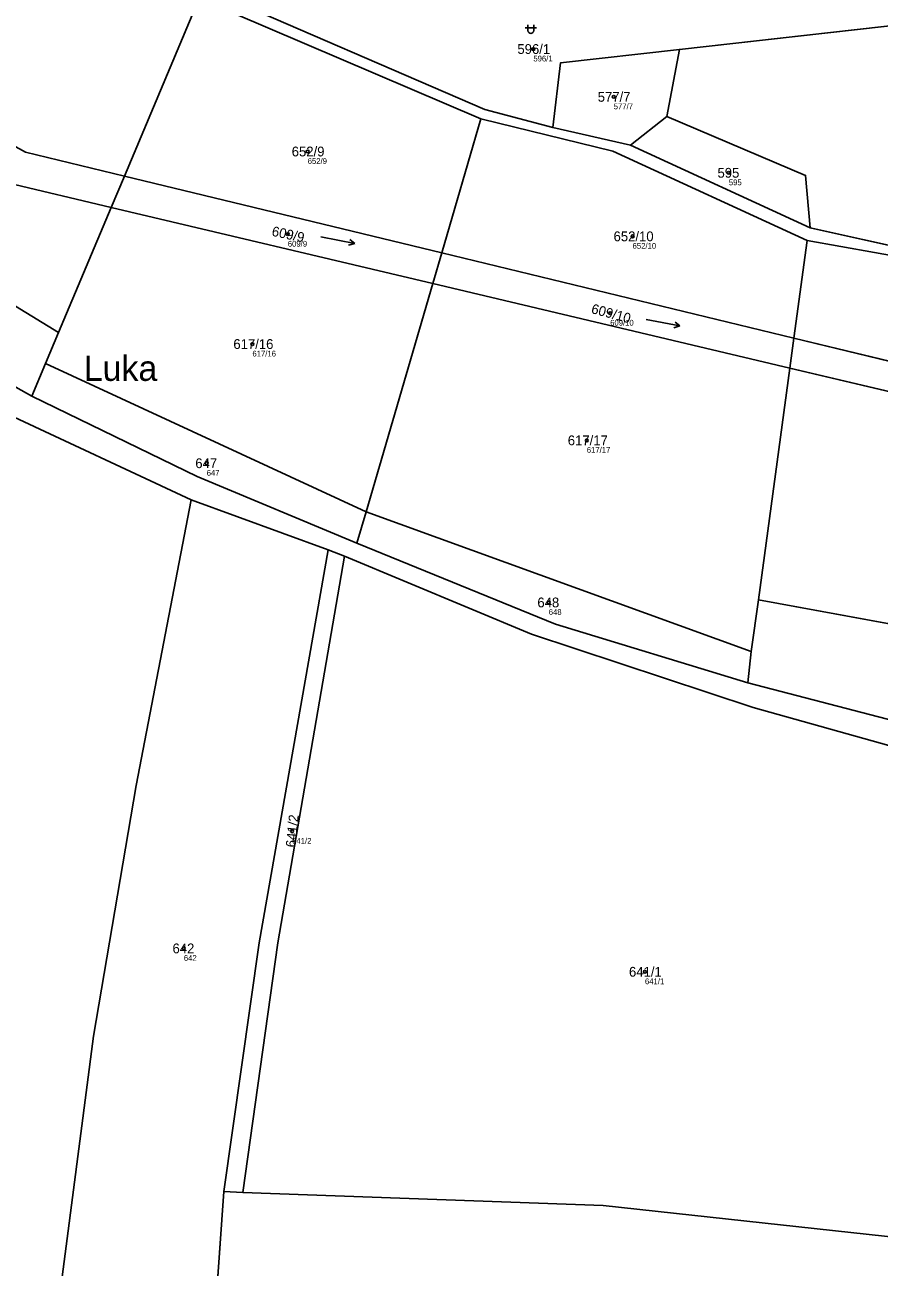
# Model space of a CAD drawing. Extents: x -767985 to -763816, y -1059600 to -1057360.
# Drawn here: x -764998 to -764849.6, y -1059284.4 to -1059068.8 of the extents above; entities that cross this region are included whole.
import ezdxf

# ---------------------------------------------------------------- set-up
doc = ezdxf.new("R2010")
doc.units = 0
for name, color, linetype in [('Definiční body', 7, 'Continuous'), ('Hranice parcel', 7, 'Continuous'), ('Parcelní čísla', 7, 'Continuous'), ('Polygon parcely', 7, 'Continuous'), ('Pop  PČ popisy', 7, 'Continuous'), ('Značky kultur', 7, 'Continuous')]:
    doc.layers.add(name, color=color, linetype=linetype)

msp = doc.modelspace()

# ---------------------------------------------------------------- linework, layer by layer
at = {"layer": 'Definiční body'}
for centre in [(-764909.65, -1059072.95994), (-764895.7, -1059081.25994), (-764948.84, -1059090.74994), (-764875.7, -1059094.44994), (-764952.29, -1059105.10994), (-764892.42, -1059105.47994), (-764896.31, -1059118.81994), (-764958.44, -1059124.17994), (-764900.37, -1059140.89994), (-764966.38, -1059144.86994), (-764906.98, -1059169.03994), (-764951.54, -1059208.76994), (-764970.34, -1059229.09994), (-764890.27, -1059233.15994)]:
    msp.add_circle(centre, 0.25, dxfattribs=at)
at = {"layer": 'Hranice parcel'}
for p, q in [((-764756.52, -1059058.65), (-764884.29, -1059073.04)), ((-764980.66, -1059095.02), (-764967.66, -1059064.11)), ((-764967.66, -1059064.11), (-764918.75, -1059085.08)), ((-764886.5, -1059084.66), (-764884.29, -1059073.04)), ((-764925.55, -1059108.35), (-764918.75, -1059085.08)), ((-764892.8, -1059089.65), (-764886.5, -1059084.66)), ((-764886.5, -1059084.66), (-764862.38, -1059094.9)), ((-764892.8, -1059089.65), (-764906.25, -1059086.6)), ((-764861.6, -1059104.01), (-764892.8, -1059089.65)), ((-764980.66, -1059095.02), (-764982.96, -1059100.47)), ((-764925.55, -1059108.35), (-764980.66, -1059095.02)), ((-764862.38, -1059094.9), (-764861.6, -1059104.01)), ((-764992.09, -1059122.18), (-764982.96, -1059100.47)), ((-764982.96, -1059100.47), (-764927.11, -1059113.69)), ((-764807.24, -1059116.05), (-764861.6, -1059104.01)), ((-764864.39, -1059123.15), (-764862.08, -1059106.19)), ((-764927.11, -1059113.69), (-764925.55, -1059108.35)), ((-764864.39, -1059123.15), (-764925.55, -1059108.35)), ((-764938.69, -1059153.28), (-764927.11, -1059113.69)), ((-764927.11, -1059113.69), (-764865.1, -1059128.36)), ((-764992.09, -1059122.18), (-764994.36, -1059127.58)), ((-764865.1, -1059128.36), (-764864.39, -1059123.15)), ((-764809.41, -1059136.46), (-764864.39, -1059123.15)), ((-764996.73, -1059133.21), (-764994.36, -1059127.58)), ((-764994.36, -1059127.58), (-764938.69, -1059153.28)), ((-764870.58, -1059168.56), (-764865.1, -1059128.36)), ((-764865.1, -1059128.36), (-764809.95, -1059141.41)), ((-764969.08, -1059151.21), (-764945.3, -1059159.91)), ((-764940.29, -1059158.74), (-764938.69, -1059153.28)), ((-764938.69, -1059153.28), (-764871.81, -1059177.56)), ((-764945.3, -1059159.91), (-764942.47, -1059160.99)), ((-764871.81, -1059177.56), (-764870.58, -1059168.56)), ((-764870.58, -1059168.56), (-764814.01, -1059178.97)), ((-764872.39, -1059183.02), (-764871.81, -1059177.56)), ((-764963.4, -1059271.33), (-764965.58, -1059302.41)), ((-764960.13, -1059271.45), (-764963.4, -1059271.33))]:
    msp.add_line(p, q, dxfattribs=at)
for points in [[(-764980.66, -1059095.02), (-764997.85, -1059090.86), (-765067.56, -1059052.35)], [(-764982.96, -1059100.47), (-765000.98, -1059096.21), (-765069.38, -1059057.63)], [(-764906.25, -1059086.6), (-764918.06, -1059083.43), (-764966.27, -1059062.57)], [(-765073.63, -1059069.94), (-765019.49, -1059105.46), (-764992.09, -1059122.18)], [(-764884.29, -1059073.04), (-764904.96, -1059075.37), (-764906.25, -1059086.6)], [(-764996.73, -1059133.21), (-765012.05, -1059124.66), (-765078.11, -1059082.38)], [(-764918.75, -1059085.08), (-764895.84, -1059090.69), (-764862.08, -1059106.19)], [(-764862.08, -1059106.19), (-764838.7, -1059110.37), (-764809.54, -1059118.72), (-764808.5, -1059128.14)], [(-764969.08, -1059151.21), (-765001.55, -1059136.08), (-765045.15, -1059110.12)], [(-764940.29, -1059158.74), (-764968.04, -1059147.17), (-764996.73, -1059133.21)], [(-764993.16, -1059299.02), (-764986.03, -1059244.31), (-764978.64, -1059200.79), (-764969.08, -1059151.21)], [(-764945.3, -1059159.91), (-764957.28, -1059228.13), (-764963.4, -1059271.33)], [(-764872.39, -1059183.02), (-764905.79, -1059172.81), (-764940.29, -1059158.74)], [(-764942.47, -1059160.99), (-764954.01, -1059228.12), (-764960.13, -1059271.45)], [(-764942.47, -1059160.99), (-764909.95, -1059174.57), (-764871.48, -1059187.27), (-764846.5, -1059194.25), (-764815.46, -1059201.74)], [(-764815.93, -1059196.03), (-764845.49, -1059190.02), (-764872.39, -1059183.02)], [(-764823.73, -1059281.76), (-764897.51, -1059273.71), (-764960.13, -1059271.45)]]:
    msp.add_lwpolyline(points, dxfattribs=at)
at = {"layer": 'Polygon parcely'}
for points in [[(-764966.27, -1059062.57), (-765060.07, -1059031.27), (-765151.17, -1058992.96), (-765171.68, -1058981.24), (-765190.33, -1058964.43), (-765190.34, -1058968.18), (-765173.39, -1058982.83), (-765152.48, -1058995.15), (-765060.83, -1059032.86), (-764967.66, -1059064.11), (-764918.75, -1059085.08), (-764895.84, -1059090.69), (-764862.08, -1059106.19), (-764838.7, -1059110.37), (-764809.54, -1059118.72), (-764808.5, -1059128.14), (-764806.78, -1059126.58), (-764807.24, -1059116.05), (-764861.6, -1059104.01), (-764892.8, -1059089.65), (-764906.25, -1059086.6), (-764918.06, -1059083.43)], [(-764980.66, -1059095.02), (-764967.66, -1059064.11), (-765060.83, -1059032.86), (-765067.56, -1059052.35), (-764997.85, -1059090.86)], [(-764752.02, -1059034.29), (-764758.51, -1059035.68), (-764764.34, -1059049.21), (-764818.31, -1059061.96), (-764833.85, -1059056.84), (-764858.96, -1059063.02), (-764885.92, -1059065.02), (-764927.24, -1059059.28), (-764957.74, -1059052.39), (-764966.27, -1059062.57), (-764918.06, -1059083.43), (-764906.25, -1059086.6), (-764904.96, -1059075.37), (-764884.29, -1059073.04), (-764756.52, -1059058.65)], [(-764980.66, -1059095.02), (-764997.85, -1059090.86), (-765067.56, -1059052.35), (-765069.38, -1059057.63), (-765000.98, -1059096.21), (-764982.96, -1059100.47)], [(-764992.09, -1059122.18), (-764982.96, -1059100.47), (-765000.98, -1059096.21), (-765069.38, -1059057.63), (-765073.63, -1059069.94), (-765019.49, -1059105.46)], [(-764862.38, -1059094.9), (-764861.6, -1059104.01), (-764807.24, -1059116.05), (-764759.08, -1059120.3), (-764757.7, -1059074.31), (-764756.52, -1059058.65), (-764884.29, -1059073.04), (-764886.5, -1059084.66)], [(-764925.55, -1059108.35), (-764918.75, -1059085.08), (-764967.66, -1059064.11), (-764980.66, -1059095.02)], [(-764996.73, -1059133.21), (-764994.36, -1059127.58), (-764992.09, -1059122.18), (-765019.49, -1059105.46), (-765073.63, -1059069.94), (-765076.21, -1059077.43), (-765078.11, -1059082.38), (-765012.05, -1059124.66)], [(-764892.8, -1059089.65), (-764886.5, -1059084.66), (-764884.29, -1059073.04), (-764904.96, -1059075.37), (-764906.25, -1059086.6)], [(-764940.29, -1059158.74), (-764968.04, -1059147.17), (-764996.73, -1059133.21), (-765012.05, -1059124.66), (-765078.11, -1059082.38), (-765079.83, -1059086.87), (-765045.15, -1059110.12), (-765001.55, -1059136.08), (-764969.08, -1059151.21), (-764945.3, -1059159.91), (-764942.47, -1059160.99), (-764909.95, -1059174.57), (-764871.48, -1059187.27), (-764846.5, -1059194.25), (-764815.46, -1059201.74), (-764815.93, -1059196.03), (-764845.49, -1059190.02), (-764872.39, -1059183.02), (-764905.79, -1059172.81)], [(-764862.08, -1059106.19), (-764895.84, -1059090.69), (-764918.75, -1059085.08), (-764925.55, -1059108.35), (-764864.39, -1059123.15)], [(-764892.8, -1059089.65), (-764861.6, -1059104.01), (-764862.38, -1059094.9), (-764886.5, -1059084.66)], [(-764982.96, -1059100.47), (-764927.11, -1059113.69), (-764925.55, -1059108.35), (-764980.66, -1059095.02)], [(-764938.69, -1059153.28), (-764927.11, -1059113.69), (-764982.96, -1059100.47), (-764992.09, -1059122.18), (-764994.36, -1059127.58)], [(-764808.5, -1059128.14), (-764809.54, -1059118.72), (-764838.7, -1059110.37), (-764862.08, -1059106.19), (-764864.39, -1059123.15), (-764809.41, -1059136.46)], [(-764864.39, -1059123.15), (-764925.55, -1059108.35), (-764927.11, -1059113.69), (-764865.1, -1059128.36)], [(-764993.16, -1059299.02), (-764986.03, -1059244.31), (-764978.64, -1059200.79), (-764969.08, -1059151.21), (-765001.55, -1059136.08), (-765045.15, -1059110.12), (-765052, -1059130.58), (-765061.13, -1059169.33), (-765065.58, -1059198.93), (-765074.87, -1059288.96)], [(-764870.58, -1059168.56), (-764865.1, -1059128.36), (-764927.11, -1059113.69), (-764938.69, -1059153.28), (-764871.81, -1059177.56)], [(-764809.41, -1059136.46), (-764864.39, -1059123.15), (-764865.1, -1059128.36), (-764809.95, -1059141.41)], [(-764940.29, -1059158.74), (-764938.69, -1059153.28), (-764994.36, -1059127.58), (-764996.73, -1059133.21), (-764968.04, -1059147.17)], [(-764814.01, -1059178.97), (-764809.95, -1059141.41), (-764865.1, -1059128.36), (-764870.58, -1059168.56)], [(-764993.16, -1059299.02), (-764965.58, -1059302.41), (-764963.4, -1059271.33), (-764957.28, -1059228.13), (-764945.3, -1059159.91), (-764969.08, -1059151.21), (-764978.64, -1059200.79), (-764986.03, -1059244.31)], [(-764871.81, -1059177.56), (-764938.69, -1059153.28), (-764940.29, -1059158.74), (-764905.79, -1059172.81), (-764872.39, -1059183.02)], [(-764945.3, -1059159.91), (-764957.28, -1059228.13), (-764963.4, -1059271.33), (-764960.13, -1059271.45), (-764954.01, -1059228.12), (-764942.47, -1059160.99)], [(-764820.28, -1059238.28), (-764815.46, -1059201.74), (-764846.5, -1059194.25), (-764871.48, -1059187.27), (-764909.95, -1059174.57), (-764942.47, -1059160.99), (-764954.01, -1059228.12), (-764960.13, -1059271.45), (-764897.51, -1059273.71), (-764823.73, -1059281.76)], [(-764815.93, -1059196.03), (-764814.01, -1059178.97), (-764870.58, -1059168.56), (-764871.81, -1059177.56), (-764872.39, -1059183.02), (-764845.49, -1059190.02)], [(-764824.88, -1059315.59), (-764823.73, -1059281.76), (-764897.51, -1059273.71), (-764960.13, -1059271.45), (-764963.4, -1059271.33), (-764965.58, -1059302.41), (-764965.02, -1059316.8)]]:
    msp.add_lwpolyline(points, close=True, dxfattribs=at)
at = {"layer": 'Značky kultur'}
for p, q in [((-764911.091, -1059069.261), (-764909.089, -1059069.261)), ((-764910.591, -1059068.761), (-764910.591, -1059069.762)), ((-764909.589, -1059069.762), (-764909.589, -1059068.761)), ((-764946.57, -1059105.579), (-764940.68, -1059106.724)), ((-764940.68, -1059106.724), (-764941.735, -1059107.03)), ((-764940.68, -1059106.724), (-764941.543, -1059106.045)), ((-764890.08, -1059119.899), (-764884.19, -1059121.044)), ((-764884.19, -1059121.044), (-764885.245, -1059121.35)), ((-764884.19, -1059121.044), (-764885.053, -1059120.365))]:
    msp.add_line(p, q, dxfattribs=at)
msp.add_arc((-764910.09, -1059069.7609), 0.5, 180, 359.9878861, dxfattribs=at)

# ---------------------------------------------------------------- texts
at = {"layer": 'Definiční body'}
for s, p in [('596/1', (-764909.65, -1059075.116)), ('577/7', (-764895.7, -1059083.416)), ('652/9', (-764948.84, -1059092.906)), ('595', (-764875.7, -1059096.606)), ('609/9', (-764952.29, -1059107.266)), ('652/10', (-764892.42, -1059107.636)), ('609/10', (-764896.31, -1059120.976)), ('617/16', (-764958.44, -1059126.336)), ('617/17', (-764900.37, -1059143.056)), ('647', (-764966.38, -1059147.026)), ('648', (-764906.98, -1059171.196)), ('641/2', (-764951.54, -1059210.926)), ('642', (-764970.34, -1059231.256)), ('641/1', (-764890.27, -1059235.316))]:
    msp.add_text(s, height=0.999996, dxfattribs=at).set_placement(p)
at = {"layer": 'Parcelní čísla'}
for s, p in [('596/1', (-764912.423, -1059073.81)), ('577/7', (-764898.473, -1059082.11)), ('652/9', (-764951.613, -1059091.6)), ('595', (-764877.674, -1059095.3)), ('652/10', (-764895.725, -1059106.33)), ('617/16', (-764961.745, -1059125.03)), ('617/17', (-764903.675, -1059141.75)), ('647', (-764968.354, -1059145.72)), ('648', (-764908.954, -1059169.89)), ('642', (-764972.314, -1059229.95)), ('641/1', (-764893.043, -1059234.01))]:
    msp.add_text(s, height=1.699998, dxfattribs=at).set_placement(p)
for s, rotation, p in [('609/9', 348, (-764955.179, -1059105.364)), ('609/10', 345, (-764899.723, -1059118.785)), ('641/2', 84, (-764950.984, -1059211.617))]:
    msp.add_text(s, height=1.699998, rotation=rotation, dxfattribs=at).set_placement(p)
at = {"layer": 'Pop  PČ popisy'}
msp.add_text('Luka', height=4.399998, dxfattribs=at).set_placement((-764987.72, -1059130.57))

doc.saveas('drawing.dxf')
